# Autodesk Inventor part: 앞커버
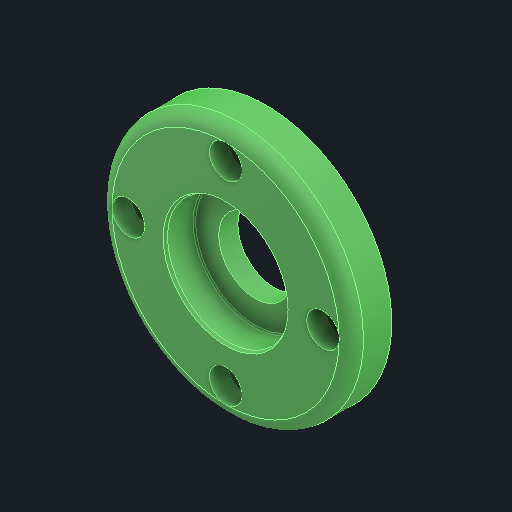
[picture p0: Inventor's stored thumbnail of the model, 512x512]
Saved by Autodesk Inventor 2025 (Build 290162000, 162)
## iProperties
Created: 2025-08
Part Number: 앞커버
Material: 알루미늄 6061
Document SubType Name: Modeling
Designer: infra11
Density: 2.71 g/cm^3
Appearance: 기본값
Author: jhkim
Sending System: Autodesk Inventor 2026
Preprocessor: ST-DEVELOPER v20.1
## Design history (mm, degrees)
feature "솔리드1"
node "솔리드2"
